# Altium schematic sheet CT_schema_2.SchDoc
size 276 x 169 mm
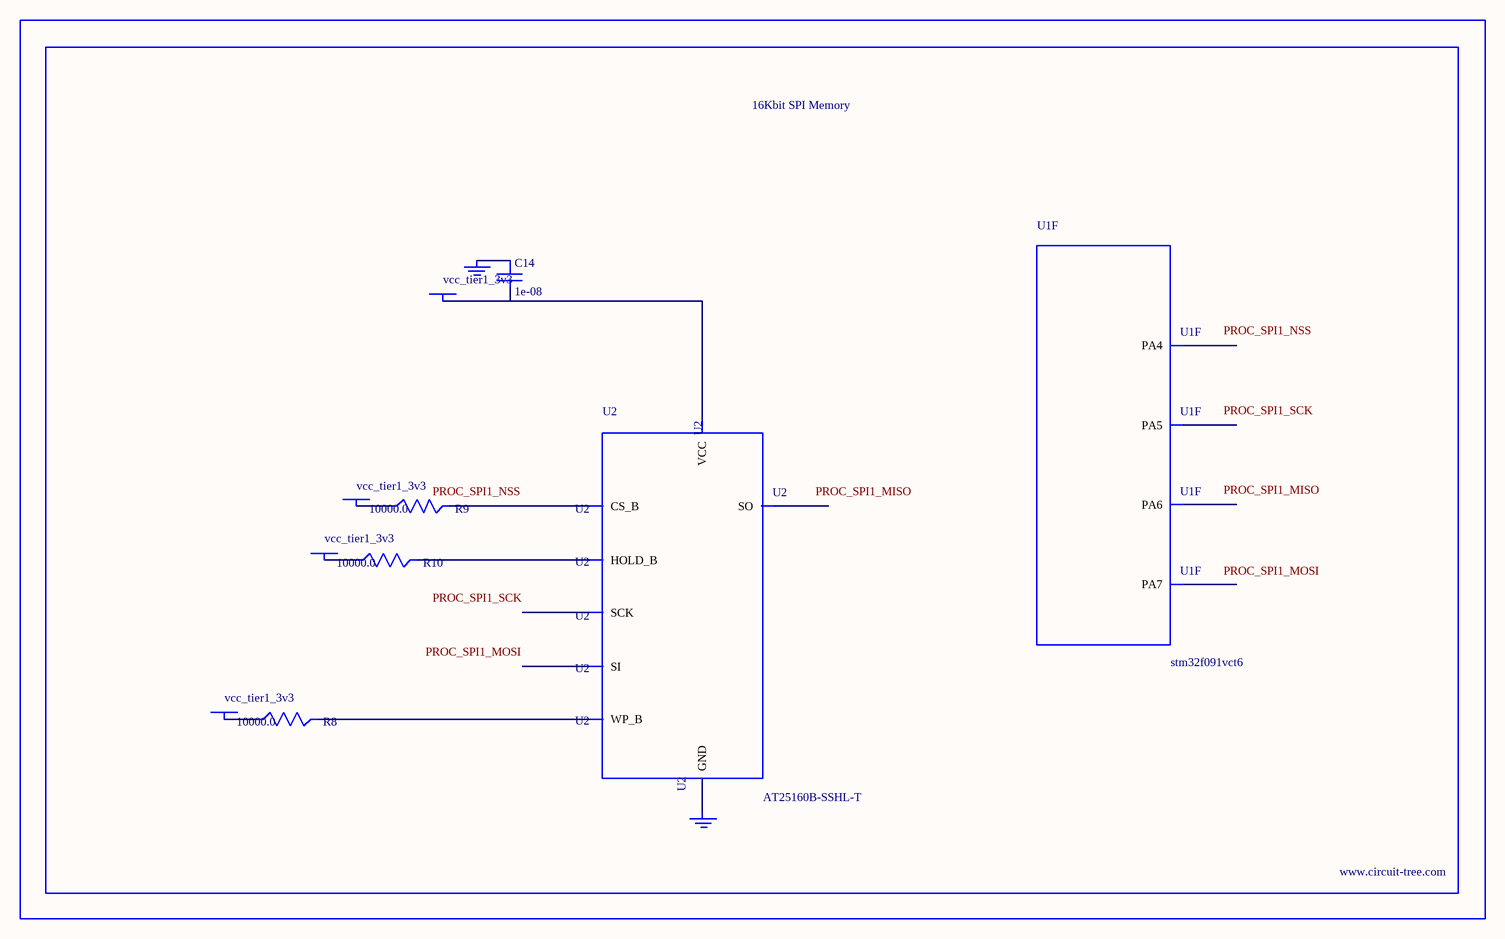
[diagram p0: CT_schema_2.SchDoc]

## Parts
BORDER1  (no value)
C14  1e-08  [C0402]
GND_INSTANCE_1_0  (no value)
GND_INSTANCE_1_1  (no value)
POWER_INSTANCE_1_0  vcc_tier1_3v3
POWER_INSTANCE_1_1  vcc_tier1_3v3
POWER_INSTANCE_1_2  vcc_tier1_3v3
POWER_INSTANCE_1_3  vcc_tier1_3v3
R8  10000.0  [R0603]
R9  10000.0  [R0603]
R10  10000.0  [R0603]
U1  stm32f091vct6  [LQFP100]  (part F of 9)
U2  AT25160B-SSHL-T  [SOIC-8]

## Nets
NetC14_1: C14.1 GND_INSTANCE_1_0.0(GND)
NetC14_2: C14.2 POWER_INSTANCE_1_3.0(PWR) U2.8(VCC)
NetGND_INSTANCE_1_1_0: GND_INSTANCE_1_1.0(GND) U2.4(GND)
NetPOWER_INSTANCE_1_0_0: POWER_INSTANCE_1_0.0(PWR) R9.1
NetPOWER_INSTANCE_1_1_0: POWER_INSTANCE_1_1.0(PWR) R8.1
NetPOWER_INSTANCE_1_2_0: POWER_INSTANCE_1_2.0(PWR) R10.1
NetR8_2: R8.2 U2.3(WP_B)
NetR9_2: R9.2 U2.1(CS_B)
NetR10_2: R10.2 U2.7(HOLD_B)

Not connected (* = marked no-connect by the designer): U1 29(PA4) 30(PA5) 31(PA6) 32(PA7); U2 2(SO) 5(SI) 6(SCK)

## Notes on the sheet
- Labels drawn without touching a wire or pin: PROC_SPI1_MISO, PROC_SPI1_MOSI, PROC_SPI1_NSS, PROC_SPI1_SCK

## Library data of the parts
BORDER1 = BORDER_PAGE1
C14 = C0402C103K3RAC
GND_INSTANCE_1_0 GND_INSTANCE_1_1 = GND
POWER_INSTANCE_1_0-POWER_INSTANCE_1_3 = PWR
R8-R10 = RC0603JR-0710KL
